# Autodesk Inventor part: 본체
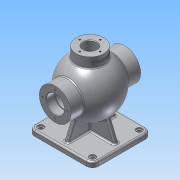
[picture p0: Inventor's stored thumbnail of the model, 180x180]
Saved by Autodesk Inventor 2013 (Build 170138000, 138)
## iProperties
Created: 2018-06
Part Number: 본체
Material: 알루미늄 6061
Document SubType Name: Modeling
Designer: Administrator
Density: 2.71 g/cm^3
Mass: 1509.52 g
Surface Area: 1153.86 cm^2
Volume: 557.018 cm^3
Author: Administrator
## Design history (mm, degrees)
sketch "스케치1"
  geometry: L1 (-68, 0)-(68, 0); L2 (-68, 17.5)-(-68, 31); L3 (-68, 31)-(-42.988, 31); L4 (42.988, 31)-(68, 31); L5 (68, 31)-(68, 17.5); L6 (68, 17.5)-(39.278, 17.5); L7 (-68, 17.5)-(-39.278, 17.5); A1 r 43 centre (0, 0) between (39.278, 17.5) and (-39.278, 17.5); A2 r 53 centre (0, 0) between (42.988, 31) and (-42.988, 31); 2 further points
  constraints: 14 end point, 4 point on circle, 3 coincident, 3 perpendicular, 2 centre point, 2 equal length, 1 collinear, 1 horizontal, 1 midpoint, 1 parallel, 1 point on line
  dimensions: "d2" = 136 distance of L1.start L1.end; "d7" = 86 diameter of A1; "d9" = 136 distance between parallel lines of L2 L5; "d13" = 62 diameter of L3 L1; "d14" = 35 diameter of L7 L1; "d16" = 106 diameter of A2
revolve "회전1" sketch "스케치1" stored, may be unused: angle "d17" = 90 deg
node "작업 평면1"
sketch "스케치2"
  geometry: L1 (-57.5, 62.5)-(57.5, 62.5); L2 (57.5, 62.5)-(57.5, -62.5); L3 (57.5, -62.5)-(-57.5, -62.5); L4 (-57.5, -62.5)-(-57.5, 62.5); L5 (-57.5, 62.5)-(57.5, -62.5); L6 (57.5, 62.5)-(-57.5, -62.5); 1 further point
  constraints: 12 end point, 2 midpoint, 2 parallel, 1 horizontal, 1 perpendicular
  dimensions: "d19" = 115 distance of L1.start L1.end; "d21" = 125 distance of L1.end L2.end
extrude "돌출1" join sketch "스케치2" distance "d22" = 10; taper "d23" = 0 deg
node "작업 평면2"
sketch "스케치3"
  geometry: C1 r 27 at (0, 0); 1 further point
  constraints: 1 centre point, 1 coincident
  dimensions: "d25" = 54 diameter of C1
extrude "돌출2" join sketch "스케치3" stored distance "d26" = 10; taper "d27" = 0 deg
sketch "스케치4"
  geometry: C1 r 27 at (0, 0) reference; C2 r 13 at (0, 0)
  constraints: 1 centre point, 1 coincident
  dimensions: "d28" = 26 diameter of C2
extrude "돌출3" cut sketch "스케치4" stored distance "d29" = 10; taper "d30" = 0 deg
sketch "스케치5"
  geometry: C1 r 13 at (0, 0) reference; 1 further point
  constraints: 1 vertical alignment
  dimensions: "d31" = 20 distance of C1.centre point (0, 20)
hole "구멍1" sketch "스케치5" at (0, 20) diameter "d32" = 3.242; stored, may be unused: countersink angle "d36" = 90 deg, drill point angle "d38" = 118 deg; dims "d33" = 9, "d34" = 4, "d35" = 2, "d37" = 11
sketch "스케치6"
  geometry: C1 r 31 at (0, 0) reference; 1 further point
  constraints: 1 vertical alignment
  dimensions: "d42" = 24 distance of C1.centre point (0, 24)
hole "구멍2" sketch "스케치6" at (0, 24) diameter "d43" = 3.242; stored, may be unused: countersink angle "d47" = 90 deg, drill point angle "d49" = 118 deg; dims "d44" = 16, "d45" = 4, "d46" = 2, "d48" = 19
sketch "스케치7"
  geometry: C1 r 17.5 at (0, 0) reference; 1 further point
  constraints: 1 vertical alignment
  dimensions: "d53" = 22.5 distance of C1.centre point (0, 22.5)
hole "구멍3" sketch "스케치7" at (0, 22.5) diameter "d54" = 3.242; stored, may be unused: countersink angle "d58" = 90 deg, drill point angle "d60" = 118 deg; dims "d55" = 12, "d56" = 4, "d57" = 2, "d59" = 15
sketch "스케치8"
  geometry: L1 (-47.5, 4)-(47.5, 4); L2 (47.5, 4)-(47.5, -4); L3 (47.5, -4)-(-47.5, -4); L4 (-47.5, -4)-(-47.5, 4); L5 (-47.5, 4)-(47.5, -4); L6 (47.5, 4)-(-47.5, -4); 1 further point
  constraints: 12 end point, 2 midpoint, 2 parallel, 1 horizontal, 1 perpendicular
  dimensions: "d64" = 95 distance of L1.start L1.end; "d66" = 8 distance of L3.end L1.start
extrude "돌출4" join sketch "스케치8" stored distance "d67" = 10; taper "d68" = 0 deg
feature "면 기울기1" dims angle "d69" = 22 deg
feature "면 기울기2" dims angle "d70" = 22 deg
sketch "스케치9"
  geometry: L1 (-4, 52.5)-(4, 52.5); L2 (4, 52.5)-(4, -52.5); L3 (4, -52.5)-(-4, -52.5); L4 (-4, -52.5)-(-4, 52.5); L5 (-4, 52.5)-(4, -52.5); L6 (4, 52.5)-(-4, -52.5); 1 further point
  constraints: 12 end point, 2 midpoint, 2 parallel, 1 horizontal, 1 perpendicular
  dimensions: "d71" = 8 distance of L1.start L1.end; "d73" = 105 distance of L1.end L2.end
extrude "돌출5" join sketch "스케치9" stored distance "d74" = 10; taper "d75" = 0 deg
feature "면 기울기3" dims angle "d76" = 22 deg
fillet "모깎기1" dims "d77" = 12
fillet "모깎기2" dims "d78" = 3
node "작업 평면3"
sketch "스케치11"
  geometry: C1 r 6 at (-45.5, 50.5); A1 r 9 centre (-45.5, 50.5) between (-45.5, 59.5) and (-54.5, 50.5) reference; 1 further point
  constraints: 1 centre point, 1 coincident
  dimensions: "d83" = 12 diameter of C1
extrude "돌출7" cut sketch "스케치11" distance "d85" = 3; taper "d86" = 0 deg
sketch "스케치12"
  geometry: C1 r 6 at (0, 0) reference; C2 r 4 at (0, 0); 1 further point
  constraints: 1 centre point, 1 coincident
  dimensions: "d87" = 8 diameter of C2
extrude "돌출8" cut sketch "스케치12" stored distance "d88" = 3; taper "d89" = 0 deg
chamfer "모따기1" distance "d90" = 1; stored, may be unused: second distance "d91" = 2, angle "d92" = 45 deg
fillet "모깎기3" dims "d93" = 3
fillet "모깎기4" dims "d94" = 3
node "작업 평면5"
sketch "스케치14"
  geometry: C1 r 18.5 at (0, 0); 1 further point
  constraints: 1 centre point, 1 coincident
  dimensions: "d100" = 37 diameter of C1
extrude "돌출9" cut sketch "스케치14" distance "d101" = 1.75; taper "d102" = 0 deg
node "작업 평면7"
sketch "스케치17"
  geometry: L1 (-27, 0)-(27, 0) reference; 2 further points
  constraints: 1 other
  dimensions: "d107" = 10 distance from line of point (0, -10) L1; "d108" = 27 horizontal distance of point (0, -10) L1.start
feature "엠보싱3" sketch "스케치17" dims "d109" = 0.5, "d110" = 0
node "솔리드1"
pattern_circular "원형 패턴1" dims angle "d40" = 360 deg
pattern_circular "원형 패턴2" dims angle "d51" = 360 deg
pattern_circular "원형 패턴3" dims angle "d62" = 360 deg
mirror "대칭1"
mirror "대칭2"
other parameters: "d8" = 106, "d18" = -85, "d79" = -16, "d99" = -16
